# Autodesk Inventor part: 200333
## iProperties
Created: 2007-10
Part Number: 200333
Document SubType Name: Modeling
Designer: TH
Density: 8.08 g/cm^3
Mass: 247.346 g
Surface Area: 113.8 cm^2
Volume: 30.6121 cm^3
Material: Stainless Steel
Description: BALL SCREW SHAFT
Component Category: Lower Component
Author: TH
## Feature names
1. Revolution1
2. Chamfer1
3. Chamfer2
